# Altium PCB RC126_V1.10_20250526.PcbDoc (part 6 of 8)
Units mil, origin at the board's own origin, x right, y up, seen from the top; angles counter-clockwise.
Board outline 6299.62 x 3544.12 mil, 4 copper layers (Top, GND, Power, Bottom), stack 35.4 mil thick; 509 components, 417 nets, 1867 pads, 2150 vias.
Unrouted connection lines stored in the file: 1451.
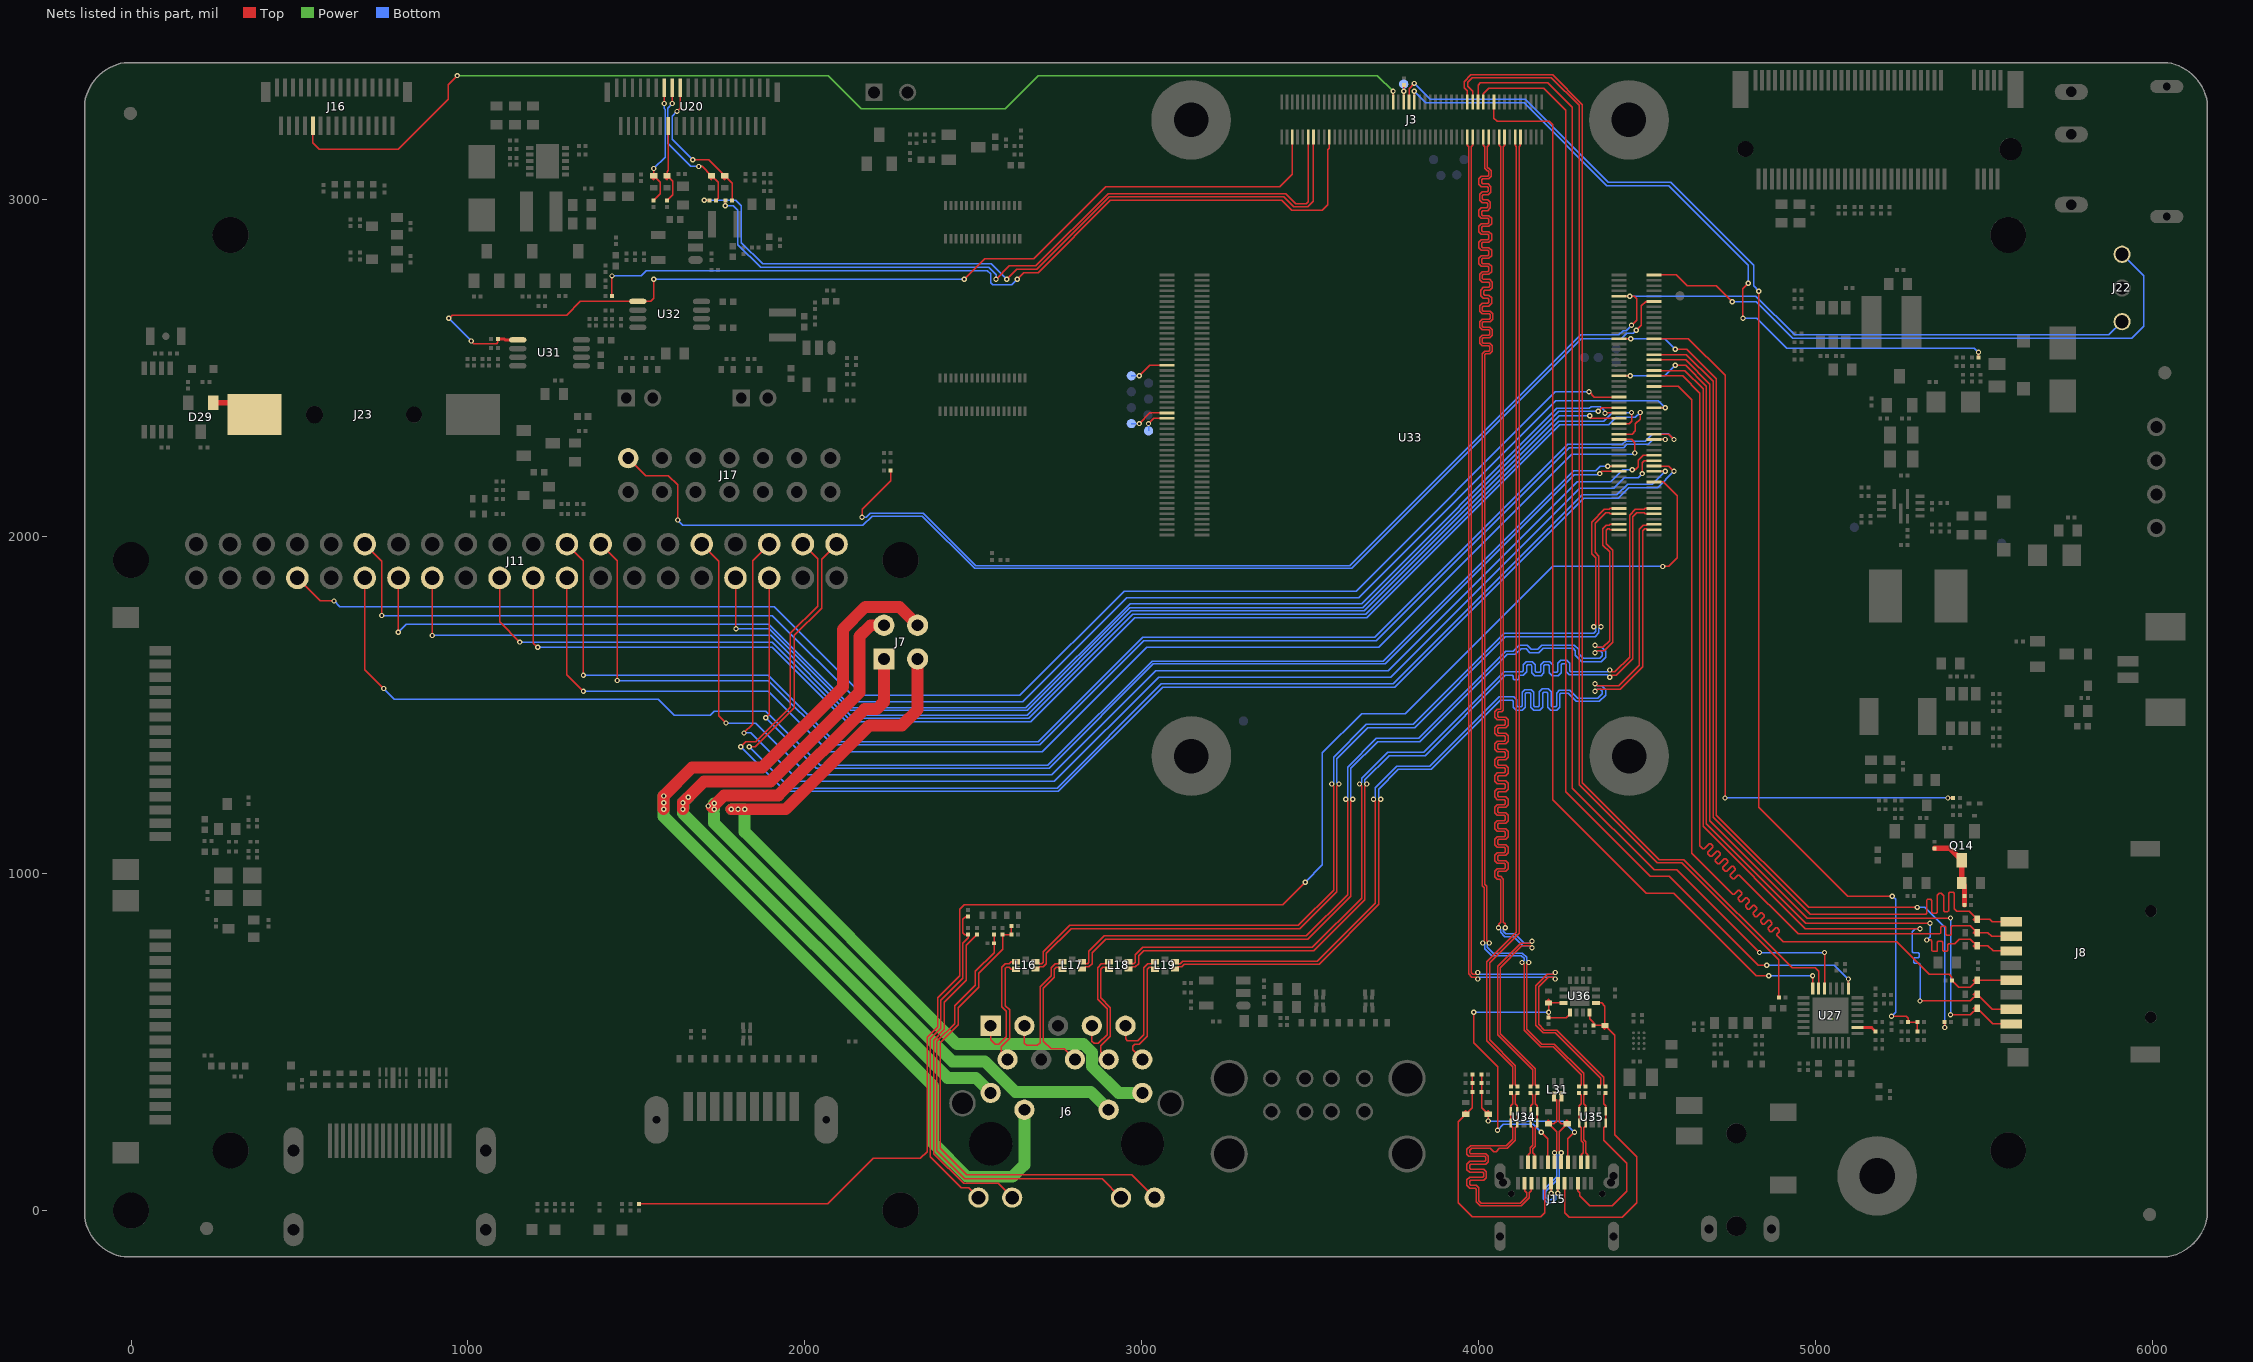
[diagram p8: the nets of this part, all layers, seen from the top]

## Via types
v1: diameter 15.75, hole 7.87, Top to Bottom, 2047 vias
v2: diameter 19.68, hole 11.81, Top to Bottom, 103 vias

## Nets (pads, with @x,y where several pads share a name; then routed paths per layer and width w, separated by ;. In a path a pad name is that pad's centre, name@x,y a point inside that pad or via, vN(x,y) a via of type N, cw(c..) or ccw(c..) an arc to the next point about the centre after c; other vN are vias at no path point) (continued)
PHY1_MDI0+: L16.1 U33.12 | length 2759.1
  Top w3.94: L16.1@2684.25,738.58 2690.94,738.58 2696.85,732.68 2702.76,732.68 2706.69,736.61 2706.69,767.72 2785.43,846.46 3464.43,846.46 3568.9,950.93 3568.9,1259.84 v1(3562.99,1265.75) ; v1(4340.55,1732.28) 4346.46,1738.19 4346.46,1937.01 4334.65,1948.82 4334.65,2043.31 4371.85,2080.51 4386.81,2080.51 4389.76,2083.46 U33.12@4415.35,2083.46
  Bottom w3.94: v1(3562.99,1265.75) 3568.9,1271.65 3568.9,1345.54 3666.27,1442.91 3804.98,1442.91 4074.66,1712.6 4340.41,1712.6 4346.46,1718.64 4346.46,1726.38 v1(4340.55,1732.28)
PHY1_MDI0-: L16.2 U33.10 | length 2759.1
  Top w3.94: L16.2@2684.25,716.93 2690.94,716.93 2696.85,722.83 2706.83,722.83 2716.54,732.54 2716.54,763.64 2789.51,836.61 3468.5,836.61 3578.74,946.85 3578.74,1259.84 v1(3584.65,1265.75) ; v1(4362.2,1732.28) 4356.3,1738.19 4356.3,1915.35 4356.3,1941.08 4344.49,1952.9 4344.49,2039.23 4375.93,2070.67 4386.81,2070.67 4389.76,2067.72 U33.10@4415.35,2067.72
  Bottom w3.94: v1(3584.65,1265.75) 3578.74,1271.65 3578.74,1341.47 3670.35,1433.07 3809.06,1433.07 4078.74,1702.76 4344.49,1702.76 4356.3,1714.57 4356.3,1726.38 v1(4362.2,1732.28)
PHY1_MDI1+: L17.1 U33.4 | length 2704.6
  Top w3.94: L17.1@2822.05,738.58 2826.77,738.58 2832.68,732.68 2838.44,732.68 2842.52,736.75 2842.52,769.69 2887.8,814.96 3488.19,814.96 3610.24,937.01 3610.24,1214.57 v1(3604.33,1220.47) ; v1(4344.49,1655.51) 4350.39,1661.42 4372.05,1661.42 4397.64,1687.01 4397.64,1935.04 4397.64,1958.8 4377.95,1978.49 4377.95,2019.35 4382.03,2023.43 4386.81,2023.43 4389.76,2020.47 U33.4@4415.35,2020.47
  Bottom w3.94: v1(3604.33,1220.47) 3610.24,1226.38 3610.24,1316.01 3695.8,1401.57 3820.73,1401.57 4079.58,1660.43 4102.36,1660.43 4119.09,1677.17 4143.7,1677.17 4155.51,1665.35 4174.14,1665.35 4186.94,1678.15 4283.53,1678.15 4296.26,1665.42 4296.26,1651.64 4309.12,1638.78 4359.11,1638.78 4366.14,1645.81 4366.14,1655.37 4360.1,1661.42 4350.39,1661.42 v1(4344.49,1655.51)
PHY1_MDI1-: L17.2 U33.6 | length 2737.2
  Top w3.94: L17.2@2822.05,716.93 2826.77,716.93 2832.68,722.83 2842.52,722.83 2852.36,732.68 2852.36,765.61 2891.87,805.12 3492.27,805.12 3620.08,932.93 3620.08,1214.57 v1(3625.98,1220.47) ; v1(4344.49,1677.17) 4350.39,1671.26 4367.97,1671.26 4387.8,1691.08 4387.8,1954.72 4368.11,1974.41 4368.11,2023.43 4377.95,2033.27 4386.81,2033.27 4389.76,2036.22 U33.6@4415.35,2036.22
  Bottom w3.94: v1(3625.98,1220.47) 3620.08,1226.38 3620.08,1311.94 3699.87,1391.73 3824.8,1391.73 4083.66,1650.59 4108.27,1650.59 4124.93,1667.25 4139.69,1667.25 4151.44,1655.51 4178.22,1655.51 4191.01,1668.31 4279.46,1668.31 4286.42,1661.35 4286.42,1647.57 4305.05,1628.94 4363.19,1628.94 4375.98,1641.73 4375.98,1659.45 4364.17,1671.26 4350.39,1671.26 v1(4344.49,1677.17)
PHY1_MDI2+: L18.1 U33.11 | length 2752.2
  Top w3.94: L18.1@2959.84,738.58 2964.57,738.58 2970.47,732.68 2976.24,732.68 2980.32,736.75 2980.32,759.84 3001.97,781.5 3505.91,781.5 3651.57,927.17 3651.57,1259.84 v1(3645.67,1265.75) ; v1(4387.8,1604.33) 4393.7,1598.43 4403.4,1598.43 4446.85,1641.87 4446.85,2062.94 4464.43,2080.51 4491.14,2080.51 4494.09,2083.46 U33.11@4520.08,2083.46
  Bottom w3.94: v1(3645.67,1265.75) 3651.57,1271.65 3651.57,1282.55 3729.26,1360.24 3836.47,1360.24 4075.65,1599.41 4128.94,1599.41 4131.89,1602.36 4131.89,1620.22 4140.61,1628.94 4158.6,1628.94 4167.32,1620.22 4167.32,1600.39 4170.28,1597.44 4180.12,1597.44 4183.07,1600.39 4183.07,1620.22 4191.79,1628.94 4209.79,1628.94 4218.5,1620.22 4218.5,1600.39 4221.46,1597.44 4231.3,1597.44 4234.25,1600.39 4234.25,1624.16 4242.97,1632.87 4260.97,1632.87 4269.68,1624.16 4269.68,1602.36 4272.64,1599.41 4382.87,1599.41 v1(4387.8,1604.33)
PHY1_MDI2-: L18.2 U33.9 | length 2772.9
  Top w3.94: L18.2@2959.84,716.93 2964.57,716.93 2970.47,722.83 2980.32,722.83 2990.16,732.68 2990.16,755.77 3006.05,771.65 3509.98,771.65 3661.42,923.09 3661.42,1259.84 v1(3667.32,1265.75) ; v1(4387.8,1582.68) 4393.7,1588.58 4407.48,1588.58 4456.69,1637.8 4456.69,2058.86 4468.5,2070.67 4491.14,2070.67 4494.09,2067.72 U33.9@4520.08,2067.72
  Bottom w3.94: v1(3667.32,1265.75) 3661.42,1271.65 3661.42,1278.47 3733.34,1350.39 3840.55,1350.39 4078.74,1588.58 4099.17,1588.58 4102.36,1585.39 4102.36,1578.08 4105.32,1575.13 4115.16,1575.13 4118.11,1578.08 4118.11,1585.63 4121.06,1588.58 4132.03,1588.58 4141.73,1598.29 4141.73,1616.14 4144.68,1619.09 4154.53,1619.09 4157.48,1616.14 4157.48,1596.32 4166.2,1587.6 4184.19,1587.6 4192.91,1596.32 4192.91,1616.14 4195.87,1619.09 4205.71,1619.09 4208.66,1616.14 4208.66,1596.32 4217.38,1587.6 4235.38,1587.6 4244.09,1596.32 4244.09,1620.08 4247.05,1623.03 4256.89,1623.03 4259.84,1620.08 4259.84,1598.29 4268.56,1589.57 4380.91,1589.57 v1(4387.8,1582.68)
PHY1_MDI3+: L19.1 U33.3 | length 2712.9
  Top w3.94: L19.1@3097.64,738.58 3102.36,738.58 3108.27,732.68 3114.03,732.68 3121.51,740.16 3520.53,740.16 3692.91,912.54 3692.91,1214.57 v1(3687.01,1220.47) ; v1(4344.49,1541.34) 4350.39,1547.24 4419.29,1547.24 4486.22,1614.17 4486.22,2017.38 4492.27,2023.43 4497.05,2023.43 4500,2020.47 U33.3@4520.08,2020.47
  Bottom w3.94: v1(3687.01,1220.47) 3692.91,1226.38 3692.91,1254.99 3756.82,1318.9 3854.19,1318.9 4059.9,1524.61 4103.49,1524.61 4112.2,1515.89 4112.2,1498.03 4115.16,1495.08 4125,1495.08 4127.95,1498.03 4127.95,1537.54 4136.67,1546.26 4154.67,1546.26 4163.39,1537.54 4163.39,1498.03 4166.34,1495.08 4176.18,1495.08 4179.13,1498.03 4179.13,1539.51 4187.85,1548.23 4205.85,1548.23 4214.57,1539.51 4214.57,1498.03 4217.52,1495.08 4227.36,1495.08 4230.32,1498.03 4230.32,1535.57 4239.03,1544.29 4269.75,1544.29 4293.38,1520.67 4353.21,1520.67 4366.14,1533.6 4366.14,1541.2 4360.1,1547.24 4350.39,1547.24 v1(4344.49,1541.34)
PHY1_MDI3-: L19.2 U33.5 | length 2745.8
  Top w3.94: L19.2@3097.64,716.93 3102.36,716.93 3108.27,722.83 3118.11,722.83 3125.59,730.32 3525.65,730.32 3702.76,908.46 3702.76,1214.57 v1(3708.66,1220.47) ; v1(4344.49,1562.99) 4350.39,1557.09 4415.21,1557.09 4476.38,1618.25 4476.38,2021.46 4488.19,2033.27 4497.05,2033.27 4500,2036.22 U33.5@4520.08,2036.22
  Bottom w3.94: v1(3708.66,1220.47) 3702.76,1226.38 3702.76,1250.91 3760.9,1309.06 3858.27,1309.06 4063.98,1514.76 4099.41,1514.76 4102.36,1511.81 4102.36,1493.95 4111.08,1485.24 4129.08,1485.24 4137.8,1493.95 4137.8,1533.46 4140.75,1536.42 4150.59,1536.42 4153.54,1533.46 4153.54,1493.95 4162.26,1485.24 4180.26,1485.24 4188.98,1493.95 4188.98,1535.43 4191.93,1538.39 4201.77,1538.39 4204.72,1535.43 4204.72,1493.95 4213.44,1485.24 4231.44,1485.24 4240.16,1493.95 4240.16,1531.5 4243.11,1534.45 4265.68,1534.45 4289.3,1510.83 4357.28,1510.83 4375.98,1529.53 4375.98,1545.28 4364.17,1557.09 4350.39,1557.09 v1(4344.49,1562.99)
PHY_G_LED+: J6.15 R248.1 R252.2 | length 975.5
  Top w3.94: R252.2@2484.25,872.05 2476.38,872.05 2468.5,864.17 2468.5,824.8 2474.41,818.9 R248.1@2484.25,818.9 2484.25,809.06 2468.5,793.31 2468.5,688.98 2403.54,624.02 2403.54,541.34 2372.05,509.84 2372.05,159.45 2464.17,67.32 2486.22,67.32 J6.15@2514.96,38.58
PHY_G_LED-: J6.16 R253.1 | length 989.8
  Top w3.94: R253.1@2509.84,818.9 2478.35,787.4 2478.35,683.07 2413.39,618.11 2413.39,537.4 2381.89,505.91 2381.89,169.29 2470.47,80.71 2572.83,80.71 J6.16@2614.96,38.58
PHY_MDI0+: J6.1 L16.3 | length 361.9
  Top w3.94: J6.1@2551.18,548.43 2551.18,506.89 2563.98,494.09 2575.72,494.09 2597.44,515.82 2597.44,591.4 2584.65,604.19 2584.65,658.32 2584.65,722.44 2594.49,732.28 2606.3,732.28 2612.2,738.19 L16.3@2625.98,738.19
PHY_MDI0-: J6.2 L16.4 | length 328.7
  Top w3.94: J6.2@2601.18,448.43 2582.68,466.93 2582.68,486.22 2607.28,510.83 2607.28,595.47 2594.49,608.27 2594.49,718.36 2598.57,722.44 2606.3,722.44 2612.2,716.54 L16.4@2625.98,716.54
PHY_MDI1+: J6.3 L17.3 | length 381.2
  Top w3.94: J6.3@2651.18,548.43 2651.18,496.46 2657.48,490.16 2689.96,490.16 2697.83,498.03 2697.83,664.51 2730.32,696.99 2730.32,720.47 2742.13,732.28 2751.97,732.28 2757.87,738.19 L17.3@2763.78,738.19
PHY_MDI1-: J6.6 L17.4 | length 371.6
  Top w3.94: L17.4@2763.78,716.54 2757.87,716.54 2751.97,722.44 2746.2,722.44 2740.16,716.4 2740.16,692.91 2707.68,660.43 2707.68,502.95 2730.32,480.32 2769.29,480.32 J6.6@2801.18,448.43
PHY_MDI2+: J6.7 L18.3 | length 355.7
  Top w3.94: J6.7@2851.18,548.43 2851.18,503.15 2858.27,496.06 2870.99,496.06 2896.65,521.72 2896.65,598.36 2868.11,626.9 2868.11,720.47 2879.92,732.28 2889.76,732.28 2895.67,738.19 L18.3@2901.57,738.19
PHY_MDI2-: J6.8 L18.4 | length 329.8
  Top w3.94: J6.8@2901.18,448.43 2877.95,471.65 2877.95,489.1 2906.5,517.65 2906.5,602.43 2877.95,630.98 2877.95,716.4 2884,722.44 2889.76,722.44 2895.67,716.54 L18.4@2901.57,716.54
PHY_MDI3+: J6.9 L19.3 | length 342.9
  Top w3.94: J6.9@2951.18,548.43 2951.18,509.45 2956.69,503.94 2988.05,503.94 3005.91,521.79 3005.91,720.47 3017.72,732.28 3027.56,732.28 3033.46,738.19 L19.3@3039.37,738.19
PHY_MDI3-: J6.10 L19.4 | length 334.5
  Top w3.94: J6.10@3001.18,448.43 2972.44,477.17 2972.44,488.19 2978.35,494.09 2992.13,494.09 3015.75,517.72 3015.75,590.55 3015.75,630.98 3015.75,716.4 3021.79,722.44 3027.56,722.44 3033.46,716.54 L19.4@3039.37,716.54
PHY_Y_LED+: J6.17 R238.2 R241.2 | length 1315.3
  Top w3.94: R241.2@2561.02,818.9 R238.2@2561.02,793.31 2561.02,765.75 2505.91,710.63 2505.91,668.92 2444.88,607.9 2444.88,555.12 2391.73,501.97 2391.73,177.17 2474.41,94.49 2881.89,94.49 J6.17@2937.8,38.58
PHY_Y_LED-: J6.18 R237.1 R239.2 R242.1 | length 1458.6
  Top w3.94: R242.1@2612.2,844.49 R239.2@2612.2,818.9 R237.1@2586.61,818.9 2586.61,775.59 2515.75,704.72 2515.75,663.39 2454.72,602.36 2454.72,551.18 2401.57,498.03 2401.57,185.04 2480.32,106.3 2970.08,106.3 J6.18@3037.8,38.58
PI_NLED_ACTIVITY: R227.2 U33.21 | length 4703.6
  Top w3.94: R227.2@1507.87,19.69 2066.93,19.69 2202.76,155.51 2342.52,155.51 2362.2,175.2 2362.2,513.78 2393.7,545.28 2393.7,631.89 2458.66,696.85 2458.66,893.7 2472.44,907.48 3417.32,907.48 v1(3484.25,974.41) ; U33.21@4520.08,2162.2 4547.24,2162.2 4588.58,2120.87 4588.58,1937.01 4562.99,1911.42 v1(4545.28,1911.42)
  Bottom w3.94: v1(3484.25,974.41) 3535.43,1025.59 3535.43,1358.27 3651.57,1474.41 3781.5,1474.41 4218.5,1911.42 v1(4545.28,1911.42)
PTP_CLKIN: P11.1 U33.166 | length 119.3
  Top w3.94: v1(2991.73,2477.17) 3023.23,2508.66 U33.166@3074.8,2508.66
  Bottom w3.94: P11.1@2968.5,2477.17 v1(2991.73,2477.17)
PWM1_CH0_M2: J11.13 U33.48 | length 4276.9
  Top w3.94: v1(793.31,1716.54) 793.31,1784.06 793.7,1784.45 J11.13@793.7,1877.56 ; v1(4374.02,2366.14) 4374.8,2366.93 U33.48@4415.35,2366.93
  Bottom w3.94: v1(793.31,1716.54) 816.93,1740.16 1891.79,1740.16 2139.82,1492.13 2655.66,1492.13 2964.72,1801.18 3651.57,1801.18 4230.93,2380.53 4327.38,2380.53 4332.68,2385.83 4360.04,2385.83 4369.91,2375.96 v1(4374.02,2366.14)
PWRON_L: J22.3 U33.99 | length 1785.6
  Top w3.94: U33.99@4520.08,2776.38 4585.83,2776.38 4618.11,2744.09 4704.72,2744.09 v1(4751.97,2696.85)
  Bottom w3.94: v1(4751.97,2696.85) 4822.83,2696.85 4931.1,2588.58 5937.4,2588.58 5972.83,2624.02 5972.83,2773.62 J22.3@5908.66,2837.8
REF_CLK0_OUT_1V8: J3.57 J16.22 | length 3512.5
  Top w3.94: J16.22@539.37,3219.5 539.37,3169.49 559.25,3149.61 793.31,3149.61 940.94,3297.24 940.94,3340.55 v1(968.5,3368.11) ; J3.57@3745.28,3289.77 3745.28,3290.9 v1(3745.28,3321.26)
  Power w3.94: v1(968.5,3368.11) 2068.9,3368.11 2167.32,3269.69 2594.49,3269.69 2692.91,3368.11 3698.43,3368.11 v1(3745.28,3321.26)
RESET_L: J22.1 R218.2 U33.92 | length 4490.1
  Top w3.94: v1(2169.29,2057.09) 2169.29,2080.71 2253.94,2165.35 R218.2@2253.94,2196.85 ; U33.92@4415.35,2713.39 v1(4447.24,2713.39) 4460.63,2713.39 4468.5,2705.51 4468.5,2642.52 v1(4452.76,2626.77)
  Bottom w3.94: v1(2169.29,2057.09) 2181.57,2057.09 2193.38,2068.9 2351.05,2068.9 2506.56,1913.39 3616.71,1913.39 4301.75,2598.43 4415.65,2598.43 4428.79,2611.56 4437.55,2611.56 v1(4452.76,2626.77) ; v1(4447.24,2713.39) 4822.05,2713.39 4937.01,2598.43 5869.29,2598.43 J22.1@5908.66,2637.8
RIN1_ES8388: C248.1 U27.23 | length 58
  Top w7.87: U27.23@5124.02,543.31 5165.35,543.31 C248.1@5177.17,531.5
RTC_BATTERY: D29.1 J23.1 | length 137
  Top w15.75: D29.1@244.09,2397.64 320.87,2397.64 348.43,2370.08 357.95,2370.08 J23.1@366.22,2361.81
SAI1_LRCK_M0: J3.19 U27.7 | length 3258.9
  Top w3.94: J3.19@4044.49,3289.77 4044.49,3275.7 4044.49,3242.13 4054.33,3232.28 4208.66,3232.28 4218.5,3222.44 4218.5,1218.5 4496.06,940.94 4578.74,940.94 4822.83,696.85 v1(4860.24,696.85) ; U27.7@4990.16,659.45 v1(4990.16,696.85)
  Bottom w3.94: v1(4860.24,696.85) v1(4990.16,696.85)
SAI1_MCLK_M0: J3.23 U27.1 | length 3422.7
  Top w3.94: J3.23@4013,3289.77 4013,3302.3 4012.99,3314.17 4029.53,3330.71 4192.91,3330.71 4257.87,3265.75 4257.87,1242.13 4507.87,992.13 4564.96,992.13 4828.74,728.35 v1(4854.33,728.35) ; U27.1@5096.46,659.45 v1(5096.46,687.01)
  Bottom w3.94: v1(4854.33,728.35) 5055.12,728.35 v1(5096.46,687.01)
SAI1_SCLK_M0: J3.25 U27.5 | length 3439.5
  Top w3.94: J3.25@3997.25,3289.77 3997.25,3300.9 3997.24,3339.76 4003.94,3346.46 4204.72,3346.46 4277.56,3273.62 4277.56,1253.94 4519.68,1011.81 4586.61,1011.81 v1(4832.68,765.75) ; U27.5@5025.59,659.45 v1(5025.59,765.75)
  Bottom w3.94: v1(4832.68,765.75) v1(5025.59,765.75)
SAI1_SDI0_M0: J3.27 R276.1 | length 3371.3
  Top w3.94: J3.27@3981.5,3289.77 3981.5,3301 3981.5,3321.65 3966.54,3336.61 3966.54,3348.43 3980.32,3362.2 4214.57,3362.2 4297.24,3279.53 4297.24,1263.78 4529.53,1031.5 4602.36,1031.5 4889.76,744.09 R276.1@4889.76,631.89
SAI1_SDO0_M0: J3.29 U27.6 | length 3455
  Top w3.94: J3.29@3965.75,3289.77 3965.75,3302.2 3965.75,3323.62 3956.69,3332.68 3956.69,3350.39 3976.38,3370.08 4218.5,3370.08 4307.09,3281.5 4307.09,1269.69 4535.43,1041.34 4608.27,1041.34 4929.13,720.47 4998.03,720.47 5007.88,710.63 U27.6@5007.88,659.45
SAI2_LRCK_M0: J11.35 U33.26 | length 3377.3
  Top w3.94: v1(1883.86,1462.6) 1893.7,1472.44 J11.35@1893.7,1877.56 ; v1(4358.27,2187.01) 4364.96,2193.7 U33.26@4415.35,2193.7
  Bottom w3.94: v1(1883.86,1462.6) 2033.46,1312.99 2724.41,1312.99 3033.46,1622.05 3722.44,1622.05 4283.46,2183.07 4354.33,2183.07 v1(4358.27,2187.01)
SAI2_MCLK_M0: J11.36 U33.29 | length 3765
  Top w3.94: v1(1818.9,1417.32) 1844.49,1442.91 1844.49,1928.35 J11.36@1893.7,1977.56 ; v1(4484.25,2187.01) 4484.25,2219.29 4490.16,2225.2 U33.29@4520.08,2225.2
  Bottom w3.94: v1(1818.9,1417.32) 1838.58,1417.32 1982.28,1273.62 2740.16,1273.62 3049.21,1582.68 3738.19,1582.68 4299.21,2143.7 4399.61,2143.7 4431.1,2175.2 4472.44,2175.2 v1(4484.25,2187.01)
SAI2_SCLK_M0: J11.12 U33.49 | length 4559.6
  Top w3.94: J11.12@693.7,1977.56 744.09,1927.17 v1(744.09,1765.75) ; U33.49@4520.08,2382.68 v1(4553.15,2382.68)
  Bottom w3.94: v1(744.09,1765.75) 1903.54,1765.75 2159.45,1509.84 2645.67,1509.84 2954.72,1818.9 3643.7,1818.9 4228.35,2403.54 4532.28,2403.54 v1(4553.15,2382.68)
SAI2_SDI_M0: J11.38 U33.27 | length 4014.4
  Top w3.94: v1(1809.06,1375.98) 1824.8,1391.73 1854.33,1391.73 1956.69,1494.09 1956.69,1712.6 2037.4,1793.31 2037.4,1933.86 J11.38@1993.7,1977.56 ; U33.27@4520.08,2209.45 4562.99,2209.45 v1(4578.74,2193.7)
  Bottom w3.94: v1(1809.06,1375.98) 1940.94,1244.09 2751.97,1244.09 3061.02,1553.15 3750,1553.15 4311.02,2114.17 4413.39,2114.17 4444.88,2145.67 4530.71,2145.67 v1(4578.74,2193.7)
SAI2_SDO_M0: J11.40 U33.25 | length 3910.6
  Top w3.94: v1(1834.65,1375.98) 1852.36,1375.98 1968.5,1492.13 1968.5,1706.69 2049.21,1787.4 2049.21,1933.07 J11.40@2093.7,1977.56 ; U33.25@4520.08,2193.7 v1(4553.15,2193.7)
  Bottom w3.94: v1(1834.65,1375.98) 1956.69,1253.94 2748.03,1253.94 3057.09,1562.99 3746.06,1562.99 4307.09,2124.02 4409.45,2124.02 4440.94,2155.51 4514.96,2155.51 v1(4553.15,2193.7)
SARADC_VIN1_KEY/RECOVERY: J17.2 U33.89 | length 3625.5
  Top w3.94: J17.2@1475.59,2232.68 1527.17,2181.1 1594.49,2181.1 1622.05,2153.54 v1(1622.05,2049.21) ; v1(4466.54,2612.2) 4482.28,2627.95 4482.28,2685.04 4494.88,2697.64 U33.89@4520.08,2697.64
  Bottom w3.94: v1(1622.05,2049.21) 1637.8,2033.46 2171.49,2033.46 2199.05,2061.02 2347.77,2061.02 2503.28,1905.51 3622.9,1905.51 4304.01,2586.61 4422.74,2586.61 4439.34,2603.21 4457.54,2603.21 v1(4466.54,2612.2)
SARADC_VIN3_HP_HOOK_1V8: C281.1 J3.51 R305.2 R319.1 | length 3895.5
  Top w3.94: J3.51@3792.52,3289.77 3792.52,3302.7 3792.52,3329.13 v1(3808.27,3344.88) ; v1(4830.71,2728.35) 4830.71,1196.85 5094.49,933.07 v1(5226.38,933.07) ; v1(5224.41,576.77) 5267.72,576.77 5273.62,570.87 R305.2@5273.62,559.06 R319.1@5301.18,559.06 C281.1@5301.18,531.5
  Bottom w3.94: v1(3808.27,3344.88) 3855.91,3297.24 4137.8,3297.24 4383.86,3051.18 4568.9,3051.18 4814.96,2805.12 4814.96,2744.09 v1(4830.71,2728.35) ; v1(5224.41,576.77) 5236.22,588.58 5236.22,923.23 v1(5226.38,933.07)
SARADC_VIN5_BOM_ID: J3.53 P20.1 R72.1 | length 75.9
  Top w3.94: J3.53@3776.78,3289.77 3777.9,3288.64 3777.9,3299.17 3776.77,3300.3 v1(3776.77,3321.26) 3776.77,3339.76 R72.1@3777.56,3340.55
  Bottom w3.94: v1(3776.77,3321.26) P20.1@3776.77,3342.91
SARADC_VIN7_1V8: J3.49 R178.1 | length 2156.4
  Top w3.94: J3.49@3808.27,3289.77 3808.27,3303.6 v1(3808.27,3321.26) ; v1(4783.46,2647.64) 4783.46,2736.22 v1(4799.21,2751.97) ; R178.1@5482.28,2531.5 v1(5482.28,2547.24)
  Bottom w3.94: v1(3808.27,3321.26) 3842.13,3287.4 4133.86,3287.4 4379.92,3041.34 4562.99,3041.34 4799.21,2805.12 v1(4799.21,2751.97) ; v1(4783.46,2647.64) 4824.8,2647.64 4913.39,2559.06 5470.47,2559.06 v1(5482.28,2547.24)
SD_3V3: C171.1 C172.1 Q14.3 R31.1 R231.2 | length 230.5
  Top w15.75: R231.2@5352.36,1074.8 5397.63,1074.8 Q14.3@5433.07,1039.37 C172.1@5433.07,972.44 5440.94,964.57 C171.1@5440.94,933.07 R31.1@5440.94,907.48
SDMMC0_CLK: C170.1 D21.2 J8.5 U33.57 | length 2812.2
  Top w3.94: U33.57@4520.08,2445.67 4591.73,2445.67 4631.89,2405.51 4631.89,1060.76 4753.58,939.07 4757.75,939.07 4769.02,950.33 4773.19,950.33 4780.15,943.37 4780.15,939.19 4768.89,927.93 4768.89,923.76 4775.85,916.8 4780.03,916.8 4791.29,928.06 4795.46,928.06 4802.42,921.1 4802.42,916.92 4791.16,905.66 4791.16,901.49 4798.12,894.53 4802.3,894.53 4813.56,905.79 4817.73,905.79 4824.69,898.83 4824.69,894.65 4813.43,883.39 4813.43,879.21 4820.39,872.26 4824.57,872.26 4835.83,883.52 4840,883.52 4846.96,876.56 4846.96,872.38 4835.7,861.12 4835.7,856.94 4842.66,849.98 4846.84,849.98 4858.1,861.25 4862.28,861.25 4869.24,854.29 4869.24,850.11 4857.97,838.85 4857.97,834.67 4864.93,827.71 4869.11,827.71 4880.37,838.97 4884.55,838.97 4891.51,832.01 4891.51,827.84 4884.32,820.65 4884.32,816.47 4903.54,797.24 5240.16,797.24 5336.61,700.79 5395.67,700.79 5403.54,692.91 C170.1@5403.54,683.07 5423.23,663.39 5458.66,663.39 D21.2@5478.35,683.07 5479.13,683.86 J8.5@5579.7,683.86
SDMMC0_CMD: D17.2 J8.3 U33.62 | length 2808.4
  Top w3.94: U33.62@4415.35,2477.17 v1(4448.82,2477.17) ; v1(4582.68,2508.66) 4613.39,2508.66 4675.2,2446.85 4675.2,1147.64 4970.47,852.36 v1(5338.58,852.36) ; v1(5328.74,803.15) 5340.85,803.15 5344.49,799.51 5344.49,771.65 5346.46,769.69 5358.27,769.69 5360.24,771.65 5360.24,795.87 5363.19,798.83 5373.03,798.83 5375.98,795.87 5375.98,772.45 5378.94,769.5 5388.78,769.5 5391.73,772.45 5391.73,788.39 5394.68,791.34 5411.42,791.34 5425.2,805.12 5458.66,805.12 D17.2@5478.35,785.43 5510.63,785.43 5525.59,770.47 J8.3@5579.7,770.47
  Bottom w3.94: v1(4448.82,2477.17) 4551.18,2477.17 v1(4582.68,2508.66) ; v1(5328.74,803.15) 5338.58,812.99 v1(5338.58,852.36)
SDMMC0_D0: D20.2 J8.7 U33.63 | length 2811.1
  Top w3.94: U33.63@4520.08,2492.91 4611.42,2492.91 4665.35,2438.98 4665.35,1139.76 4968.5,836.61 v1(5309.06,836.61) ; v1(5309.06,622.05) 5458.66,622.05 D20.2@5478.35,641.73 5522.83,597.24 J8.7@5579.7,597.24
  Bottom w3.94: v1(5309.06,622.05) 5309.06,731 5305.81,734.25 5293.5,734.25 5290.55,737.2 5290.55,747.05 5293.5,750 5303.71,750 5306.67,752.95 5306.67,762.8 5303.71,765.75 5288.39,765.75 5285.43,768.7 5285.43,826.77 5295.28,836.61 v1(5309.06,836.61)
SDMMC0_D1: D19.2 J8.8 U33.67 | length 2819.2
  Top w3.94: U33.67@4520.08,2524.41 4613.39,2524.41 4685.04,2452.76 4685.04,1157.48 4974.41,868.11 v1(5399.61,868.11) ; v1(5399.61,580.71) 5458.66,580.71 D19.2@5478.35,600.39 5524.8,553.94 J8.8@5579.7,553.94
  Bottom w3.94: v1(5399.61,580.71) v1(5399.61,868.11)
SDMMC0_D2/JTAG_TCK_M0: D22.2 J8.1 U33.69 | length 2803.6
  Top w3.94: U33.69@4520.08,2540.16 4615.35,2540.16 4694.88,2460.63 4694.88,1167.32 4983.58,878.62 5325.79,878.62 5328.74,881.57 5328.74,921.26 5330.71,923.23 5340.55,923.23 5344.49,919.29 5344.49,885.19 5347.44,882.24 5357.28,882.24 5360.24,885.19 5360.24,935.04 5366.14,940.94 5372.05,940.94 5378.94,934.06 5378.94,889.76 5382.36,886.34 5389.76,886.34 5393.7,890.27 5393.7,940.94 5397.64,944.88 5407.48,944.88 5410.43,941.93 5410.43,895.67 5418.31,887.8 5454.72,887.8 D22.2@5478.35,864.17 5516.54,864.17 5523.62,857.09 J8.1@5579.7,857.09
SDMMC0_D3/JTAG_TMS_M0: D23.2 J8.2 U33.61 | length 2814.2
  Top w3.94: U33.61@4520.08,2477.17 4604.33,2477.17 4655.51,2425.98 4655.51,1082.11 4663.8,1073.82 4667.98,1073.82 4683.03,1088.87 4687.2,1088.87 4694.16,1081.91 4694.16,1077.73 4679.11,1062.68 4679.11,1058.51 4686.07,1051.55 4690.25,1051.55 4705.3,1066.59 4709.47,1066.59 4716.43,1059.64 4716.43,1055.46 4701.38,1040.41 4701.38,1036.24 4708.34,1029.28 4712.52,1029.28 4727.57,1044.32 4731.74,1044.32 4738.7,1037.36 4738.7,1033.19 4723.66,1018.14 4723.66,1013.96 4730.62,1007 4734.79,1007 4749.84,1022.05 4754.02,1022.05 4760.98,1015.09 4760.98,1010.92 4745.93,995.87 4745.93,991.69 4752.89,984.73 4757.06,984.73 4767.93,995.61 4772.11,995.61 4946.85,820.87 5368.11,820.87 5370.08,822.83 5370.08,841.37 5373.03,844.32 5382.87,844.32 5385.83,841.37 5385.83,819.29 5388.78,816.34 5398.62,816.34 5401.57,819.29 5401.57,841.54 5404.53,844.49 5458.66,844.49 D23.2@5478.35,824.8 5510.63,824.8 5521.65,813.78 J8.2@5579.7,813.78
SDMMC0_DET_L: R228.1 U33.76 | length 2761.9
  Top w3.94: U33.76@4415.35,2587.4 v1(4450.79,2587.4) ; v1(4582.68,2555.91) 4617.32,2555.91 4704.72,2468.5 4704.72,1173.23 4978.35,899.61 v1(5301.18,899.61) ; v1(5381.89,543.31) R228.1@5381.89,559.06
  Bottom w3.94: v1(4450.79,2587.4) 4551.18,2587.4 v1(4582.68,2555.91) ; v1(5301.18,899.61) 5322.83,899.61 5381.89,840.55 v1(5381.89,543.31)
SDMMC0_PWREN_H: R230.1 U33.75 | length 2186.5
  Top w3.94: U33.75@4520.08,2587.4 4621.26,2587.4 4730.32,2478.35 v1(4730.32,1224.41) ; v1(5391.73,1224.41) R230.1@5407.48,1224.41
  Bottom w3.94: v1(4730.32,1224.41) v1(5391.73,1224.41)
SDS_IN_N: P5.1 U33.148 | length 119.3
  Top w3.94: v1(2991.73,2335.43) 3023.23,2366.93 U33.148@3074.8,2366.93
  Bottom w3.94: P5.1@2968.5,2335.43 v1(2991.73,2335.43)
SDS_IN_P: P4.1 U33.146 | length 83.9
  Top w3.94: v1(3019.29,2335.43) 3035.04,2351.18 U33.146@3074.8,2351.18
  Bottom w3.94: v1(3019.29,2335.43) 3019.68,2335.04 P4.1@3019.68,2313.78
SPI1_CLK_M0: J11.23 U33.38 | length 3999.3
  Top w3.94: J11.23@1293.7,1877.56 1293.7,1590.55 1342.52,1541.73 v1(1342.52,1541.34) ; U33.38@4415.35,2288.19 4452.76,2288.19 4462.6,2278.35 v1(4462.6,2248.03)
  Bottom w3.94: v1(1342.52,1541.34) 1891.73,1541.34 2070.87,1362.2 2704.72,1362.2 3013.78,1671.26 3702.76,1671.26 4275.59,2244.09 4458.66,2244.09 v1(4462.6,2248.03)
SPI1_CSN0_M0: J11.24 U33.39 | length 4177.5
  Top w3.94: J11.24@1293.7,1977.56 1342.52,1928.74 v1(1342.52,1588.58) ; U33.39@4520.08,2303.94 4562.99,2303.94 v1(4578.74,2288.19)
  Bottom w3.94: v1(1342.52,1588.58) 1891.73,1588.58 2088.58,1391.73 2692.91,1391.73 3001.97,1700.79 3690.94,1700.79 4263.78,2273.62 4425.2,2273.62 4435.04,2283.46 4494.09,2283.46 4515.75,2305.12 4561.81,2305.12 v1(4578.74,2288.19)
SPI1_CSN1_M0: J11.26 U33.37 | length 4022.9
  Top w3.94: J11.26@1393.7,1977.56 1442.91,1928.35 v1(1442.91,1572.83) ; U33.37@4520.08,2288.19 v1(4553.15,2288.19)
  Bottom w3.94: v1(1442.91,1572.83) 1891.73,1572.83 2082.68,1381.89 2696.85,1381.89 3005.91,1690.94 3694.88,1690.94 4267.72,2263.78 4429.13,2263.78 4438.98,2273.62 4503.15,2273.62 4517.72,2288.19 v1(4553.15,2288.19)
SPI1_MISO_M0: J11.21 U33.40 | length 4068
  Top w3.94: J11.21@1193.7,1877.56 1193.7,1684.25 v1(1206.69,1671.26) ; U33.40@4415.35,2303.94 4454.72,2303.94 4464.57,2313.78 4464.57,2334.65 4478.35,2348.43 v1(4478.35,2368.11)
  Bottom w3.94: v1(1206.69,1671.26) 1903.54,1671.26 2124.02,1450.79 2669.29,1450.79 2978.35,1759.84 3667.32,1759.84 4240.16,2332.68 4385.83,2332.68 4407.48,2354.33 4464.57,2354.33 v1(4478.35,2368.11)
SPI1_MOSI_M0: J11.19 U33.44 | length 4050.1
  Top w3.94: J11.19@1093.7,1877.56 1093.7,1746.85 v1(1153.54,1687.01) ; U33.44@4415.35,2335.43 4445.67,2335.43 4452.76,2342.52 v1(4452.76,2368.11)
  Bottom w3.94: v1(1153.54,1687.01) 1902.64,1687.01 2129.02,1460.63 2664.18,1460.63 2973.24,1769.69 3663.39,1769.69 4236.22,2342.52 4370.32,2342.52 4395.91,2368.11 v1(4452.76,2368.11)
SPI2_CLK_M1: J11.32 U33.31 | length 3782.5
  Top w3.94: J11.32@1693.7,1977.56 1744.09,1927.17 1744.09,1468.5 v1(1765.75,1446.85) ; v1(4454.72,2198.82) 4464.57,2198.82 4472.44,2206.69 4472.44,2226.38 4487.01,2240.94 U33.31@4520.08,2240.94
  Bottom w3.94: v1(1765.75,1446.85) 1854.33,1446.85 2007.87,1293.31 2732.28,1293.31 3041.34,1602.36 3730.32,1602.36 4291.34,2163.39 4391.73,2163.39 4427.17,2198.82 v1(4454.72,2198.82)
SPI2_CSN0_M1: J11.7 U33.54 | length 4445.3
  Top w3.94: J11.7@493.7,1877.56 562.2,1809.06 v1(602.36,1809.06) ; v1(4326.77,2429.92) 4342.52,2414.17 U33.54@4415.35,2414.17
  Bottom w3.94: v1(602.36,1809.06) 620.08,1791.34 1909.45,1791.34 2171.26,1529.53 2637.8,1529.53 2946.85,1838.58 3635.83,1838.58 4227.17,2429.92 v1(4326.77,2429.92)
SPI2_CSN1_M1: J11.33 U33.50 | length 3244.3
  Top w3.94: J11.33@1793.7,1877.56 1793.7,1875.59 1795.28,1874.02 v1(1795.28,1726.38) ; v1(4354.33,2372.05) 4364.96,2382.68 U33.50@4415.35,2382.68
  Bottom w3.94: v1(1795.28,1726.38) 1894.43,1726.38 2136.56,1484.25 2658.93,1484.25 2964.04,1789.37 3654.53,1789.37 4237.21,2372.05 v1(4354.33,2372.05)
SPI2_MISO_M1: J11.15 U33.46 | length 4164.4
  Top w3.94: v1(893.7,1706.69) J11.15@893.7,1877.56 ; v1(4328.74,2358.27) 4332.68,2354.33 4331.69,2353.35 4333.86,2351.18 U33.46@4415.35,2351.18
  Bottom w3.94: v1@894.69,1707.68 v1(893.7,1706.69) 1897.81,1706.69 2134.03,1470.47 2659.08,1470.47 2968.13,1779.53 3659.45,1779.53 4238.19,2358.27 v1(4328.74,2358.27)
SPI2_MOSI_M1: J11.11 U33.28 | length 4489.5
  Top w3.94: J11.11@693.7,1877.56 693.7,1605.51 v1(750,1549.21) ; v1(4381.89,2208.66) 4382.68,2209.45 U33.28@4415.35,2209.45
  Bottom w3.94: v1(750,1549.21) 781.5,1517.72 1564.96,1517.72 1612.2,1470.47 1718.5,1470.47 1730.32,1482.28 1883.86,1482.28 2045.28,1320.87 2721.15,1320.87 3030.2,1629.92 3716.54,1629.92 4281.5,2194.88 4346.65,2194.88 4360.43,2208.66 v1(4381.89,2208.66)
SPK_CTL_H: J3.96 R333.1 U31.1 U32.1 | length 3073
  Top w3.94: v1(942.91,2647.64) 952.76,2657.48 1293.31,2657.48 1333.67,2697.84 U32.1@1503.94,2697.84 1542.33,2697.84 1551.18,2706.69 v1(1551.18,2763.78) ; v1(1009.84,2580.71) 1017.72,2572.83 1084.65,2572.83 1088.58,2576.77 R333.1@1088.58,2586.61 ; v1(2472.44,2763.78) 2533.46,2824.8 2679.13,2824.8 2891.83,3037.5 3408.76,3037.5 3446.06,3074.8 3446.06,3181.4 J3.96@3446.07,3185.83
  Top w7.87: R333.1@1088.58,2586.61 1107.29,2586.61 1110.24,2583.67 U31.1@1147.64,2583.67
  Bottom w3.94: v1(942.91,2647.64) v1(1009.84,2580.71) ; v1(1551.18,2763.78) v1(2472.44,2763.78)
SSRX1N_DP_TX_D0N: J3.12 R346.1 | length 2890
  Top w3.94: R346.1@4094.49,368.11 4100.39,374.02 4100.39,427.17 4023.62,503.94 4023.62,738.19 4111.42,825.98 4111.42,3157.48 4107.48,3161.42 J3.12@4107.48,3185.83
SSRX1P_DP_TX_D0P: J3.10 R347.1 | length 2890
  Top w3.94: R347.1@4114.17,368.11 4108.27,374.02 4108.27,430.43 4031.5,507.2 4031.5,734.93 4119.29,822.72 4119.29,3157.48 4123.23,3161.42 J3.10@4123.23,3185.83
SSRX2N_DP_TX_D2N: J3.24 R348.1 | length 3534
  Top w3.94: v1(4011.02,794.09) 4015.75,798.82 4015.75,958.47 4009.84,964.37 4009.84,2538.58 4009.84,2542.83 4017.41,2550.39 4028.54,2550.39 4031.5,2553.35 4031.5,2563.19 4028.54,2566.14 4009.53,2566.14 4001.97,2573.71 4001.97,2590.07 4009.53,2597.64 4028.54,2597.64 4031.5,2600.59 4031.5,2610.43 4028.54,2613.39 4009.53,2613.39 4001.97,2620.95 4001.97,2637.32 4009.53,2644.88 4030.51,2644.88 4033.46,2647.83 4033.46,2657.68 4030.51,2660.63 4009.53,2660.63 4001.97,2668.2 4001.97,2684.56 4009.53,2692.13 4026.57,2692.13 4029.53,2695.08 4029.53,2704.92 4026.57,2707.87 4013.47,2707.87 4005.91,2715.44 4005.91,2731.8 4013.47,2739.37 4028.54,2739.37 4031.5,2742.32 4031.5,2752.17 4028.54,2755.12 4009.53,2755.12 4001.97,2762.68 4001.97,2779.05 4009.53,2786.61 4026.57,2786.61 4029.53,2789.57 4029.53,2799.41 4026.57,2802.36 4007.57,2802.36 4000,2809.93 4000,2826.29 4007.57,2833.86 4026.57,2833.86 4029.53,2836.81 4029.53,2846.65 4026.57,2849.61 4007.57,2849.61 4000,2857.17 4000,2873.54 4007.57,2881.1 4026.57,2881.1 4029.53,2884.06 4029.53,2893.9 4026.57,2896.85 4007.57,2896.85 4000,2904.42 4000,2920.78 4007.57,2928.35 4026.57,2928.35 4029.53,2931.3 4029.53,2941.14 4026.57,2944.09 4007.57,2944.09 4000,2951.66 4000,2968.03 4007.57,2975.59 4022.64,2975.59 4025.59,2978.54 4025.59,2988.39 4022.64,2991.34 4009.53,2991.34 4001.97,2998.9 4001.97,3015.27 4009.53,3022.83 4024.61,3022.83 4027.56,3025.79 4027.56,3035.63 4024.61,3038.58 4007.57,3038.58 4000,3046.15 4000,3062.51 4007.57,3070.08 4025.79,3070.08 4028.74,3073.03 4028.74,3082.87 4025.79,3085.83 4024.49,3085.83 4016.93,3093.39 4016.93,3157.48 4012.99,3161.42 J3.24@4013,3185.83 ; v1(4127.95,736.22) 4133.86,730.32 4133.86,535.43 4183.07,486.22 4220.47,486.22 4303.15,403.54 4303.15,374.02 R348.1@4297.24,368.11
  Bottom w3.94: v1(4011.02,794.09) 4016.93,788.19 4016.93,777.56 4038.58,755.91 4125.98,755.91 4133.86,748.03 4133.86,742.13 v1(4127.95,736.22)
SSRX2P_DP_TX_D2P: J3.22 R349.1 | length 3535
  Top w3.94: J3.22@4028.74,3185.83 4028.74,3161.42 4024.8,3157.48 4024.8,3096.65 4027.76,3093.7 4029.05,3093.7 4036.61,3086.14 4036.61,3069.77 4029.05,3062.2 4010.83,3062.2 4007.87,3059.25 4007.87,3049.41 4010.83,3046.46 4027.87,3046.46 4035.43,3038.89 4035.43,3022.53 4027.87,3014.96 4012.8,3014.96 4009.84,3012.01 4009.84,3002.17 4012.8,2999.21 4025.9,2999.21 4033.46,2991.65 4033.46,2975.28 4025.9,2967.72 4010.83,2967.72 4007.87,2964.76 4007.87,2954.92 4010.83,2951.97 4029.84,2951.97 4037.4,2944.4 4037.4,2928.04 4029.84,2920.47 4010.83,2920.47 4007.87,2917.52 4007.87,2907.68 4010.83,2904.72 4029.84,2904.72 4037.4,2897.16 4037.4,2880.79 4029.84,2873.23 4010.83,2873.23 4007.87,2870.28 4007.87,2860.43 4010.83,2857.48 4029.84,2857.48 4037.4,2849.92 4037.4,2833.55 4029.84,2825.98 4010.83,2825.98 4007.87,2823.03 4007.87,2813.19 4010.83,2810.24 4029.84,2810.24 4037.4,2802.67 4037.4,2786.31 4029.84,2778.74 4012.8,2778.74 4009.84,2775.79 4009.84,2765.94 4012.8,2762.99 4031.8,2762.99 4039.37,2755.43 4039.37,2739.06 4031.8,2731.5 4016.73,2731.5 4013.78,2728.54 4013.78,2718.7 4016.73,2715.75 4029.84,2715.75 4037.4,2708.18 4037.4,2691.82 4029.84,2684.25 4012.8,2684.25 4009.84,2681.3 4009.84,2671.46 4012.8,2668.5 4033.77,2668.5 4041.34,2660.94 4041.34,2644.57 4033.77,2637.01 4012.8,2637.01 4009.84,2634.06 4009.84,2624.21 4012.8,2621.26 4031.8,2621.26 4039.37,2613.69 4039.37,2597.33 4031.8,2589.76 4012.8,2589.76 4009.84,2586.81 4009.84,2576.97 4012.8,2574.02 4031.8,2574.02 4039.37,2566.45 4039.37,2550.08 4031.8,2542.52 4020.67,2542.52 4017.72,2539.57 4017.72,2538.58 4017.72,967.63 4023.62,961.73 4023.62,801.18 v1(4030.71,794.09) ; v1(4147.64,736.22) 4141.73,730.32 4141.73,538.69 4186.33,494.09 4223.73,494.09 4311.02,406.8 4311.02,374.02 R349.1@4316.93,368.11
  Bottom w3.94: v1(4030.71,794.09) 4024.8,788.19 4024.8,780.82 4041.84,763.78 4129.25,763.78 4141.73,751.29 4141.73,750 4141.73,742.13 v1(4147.64,736.22)
SSTX1N_DP_TX_D1N: C251.1 J3.18 | length 3531.1
  Top w3.94: v1(4058.27,839.37) 4058.55,839.37 4058.55,850.39 4064.32,856.16 4064.32,980.65 4061.36,983.61 4054.81,983.61 4047.24,991.17 4047.24,1007.54 4054.81,1015.1 4075.79,1015.1 4078.74,1018.06 4078.74,1027.9 4075.79,1030.85 4054.81,1030.85 4047.24,1038.42 4047.24,1054.78 4054.81,1062.35 4075.79,1062.35 4078.74,1065.3 4078.74,1075.14 4075.79,1078.1 4054.81,1078.1 4047.24,1085.66 4047.24,1102.03 4054.81,1109.59 4075.79,1109.59 4078.74,1112.54 4078.74,1122.39 4075.79,1125.34 4054.81,1125.34 4047.24,1132.9 4047.24,1149.27 4054.81,1156.84 4075.79,1156.84 4078.74,1159.79 4078.74,1169.63 4075.79,1172.58 4054.81,1172.58 4047.24,1180.15 4047.24,1196.51 4054.81,1204.08 4075.79,1204.08 4078.74,1207.03 4078.74,1216.87 4075.79,1219.83 4054.81,1219.83 4047.24,1227.39 4047.24,1243.76 4054.81,1251.32 4075.79,1251.32 4078.74,1254.28 4078.74,1264.12 4075.79,1267.07 4054.81,1267.07 4047.24,1274.64 4047.24,1291 4054.81,1298.57 4075.79,1298.57 4078.74,1301.52 4078.74,1311.36 4075.79,1314.32 4054.81,1314.32 4047.24,1321.88 4047.24,1338.25 4054.81,1345.81 4075.79,1345.81 4078.74,1348.76 4078.74,1358.61 4075.79,1361.56 4054.81,1361.56 4047.24,1369.12 4047.24,1385.49 4054.81,1393.06 4075.79,1393.06 4078.74,1396.01 4078.74,1405.85 4075.79,1408.8 4054.81,1408.8 4047.24,1416.37 4047.24,1432.73 4054.81,1440.3 4075.79,1440.3 4078.74,1443.25 4078.74,1453.1 4075.79,1456.05 4054.81,1456.05 4047.24,1463.61 4047.24,1479.98 4054.81,1487.54 4062.99,1487.54 4064.17,1488.72 4064.17,3157.48 4060.24,3161.42 J3.18@4060.24,3185.83 ; v1(4157.48,779.53) 4151.57,785.43 4127.28,785.43 4062.99,721.15 4062.99,524.91 4167.32,420.58 4167.32,374.02 C251.1@4173.23,368.11
  Bottom w3.94: v1(4058.27,839.37) 4064.17,833.46 4064.17,826.77 4064.17,825.48 4076.66,812.99 4103.04,812.99 4130.6,785.43 4133.86,785.43 4151.57,785.43 v1(4157.48,779.53)
SSTX1P_DP_TX_D1P: C252.1 J3.16 | length 3531.6
  Top w3.94: J3.16@4075.99,3185.83 4075.98,3161.42 4072.05,3157.48 4072.05,1484.48 4067.24,1479.67 4058.07,1479.67 4055.12,1476.72 4055.12,1466.87 4058.07,1463.92 4079.05,1463.92 4086.61,1456.36 4086.61,1439.99 4079.05,1432.43 4058.07,1432.43 4055.12,1429.47 4055.12,1419.63 4058.07,1416.68 4079.05,1416.68 4086.61,1409.11 4086.61,1392.75 4079.05,1385.18 4058.07,1385.18 4055.12,1382.23 4055.12,1372.39 4058.07,1369.43 4079.05,1369.43 4086.61,1361.87 4086.61,1345.5 4079.05,1337.94 4058.07,1337.94 4055.12,1334.98 4055.12,1325.14 4058.07,1322.19 4079.05,1322.19 4086.61,1314.62 4086.61,1298.26 4079.05,1290.69 4058.07,1290.69 4055.12,1287.74 4055.12,1277.9 4058.07,1274.95 4079.05,1274.95 4086.61,1267.38 4086.61,1251.01 4079.05,1243.45 4058.07,1243.45 4055.12,1240.5 4055.12,1230.65 4058.07,1227.7 4079.05,1227.7 4086.61,1220.14 4086.61,1203.77 4079.05,1196.21 4058.07,1196.21 4055.12,1193.25 4055.12,1183.41 4058.07,1180.46 4079.05,1180.46 4086.61,1172.89 4086.61,1156.53 4079.05,1148.96 4058.07,1148.96 4055.12,1146.01 4055.12,1136.17 4058.07,1133.21 4079.05,1133.21 4086.61,1125.65 4086.61,1109.28 4079.05,1101.72 4058.07,1101.72 4055.12,1098.76 4055.12,1088.92 4058.07,1085.97 4079.05,1085.97 4086.61,1078.4 4086.61,1062.04 4079.05,1054.47 4058.07,1054.47 4055.12,1051.52 4055.12,1041.68 4058.07,1038.72 4079.05,1038.72 4086.61,1031.16 4086.61,1014.79 4079.05,1007.23 4058.07,1007.23 4055.12,1004.28 4055.12,994.43 4058.07,991.48 4064.62,991.48 4072.19,983.92 4072.19,856.16 4077.67,850.68 4077.67,839.37 v1(4077.95,839.37) ; C252.1@4153.54,368.11 4159.45,374.02 4159.45,417.32 4055.12,521.65 4055.12,724.41 4124.02,793.31 4151.57,793.31 v1(4157.48,799.21)
  Bottom w3.94: v1(4077.95,839.37) 4072.05,833.46 4072.05,828.74 4079.92,820.87 4106.3,820.87 4133.86,793.31 4151.57,793.31 v1(4157.48,799.21)
SSTX2N_DP_TX_D3N: C253.1 J3.30 | length 3216.2
  Top w3.94: J3.30@3965.75,3185.83 3965.75,3182.5 3965.75,3161.42 3969.69,3157.48 3969.69,702.25 3979.02,692.91 3990.16,692.91 v1(3996.06,687.01) ; v1(4226.38,687.01) 4220.47,692.91 4206.02,692.91 4177.17,664.06 4177.17,552.47 4194.21,535.43 4230.32,535.43 4370.08,395.67 4370.08,374.02 C253.1@4375.98,368.11
  Bottom w3.94: v1(3996.06,687.01) 4001.97,692.91 4220.47,692.91 v1(4226.38,687.01)
SSTX2P_DP_TX_D3P: C254.1 J3.28 | length 3217.3
  Top w3.94: J3.28@3981.5,3185.83 3981.5,3179.9 3981.5,3161.42 3977.56,3157.48 3977.56,705.51 3982.28,700.79 3990.16,700.79 v1(3996.06,706.69) ; v1(4226.38,706.69) 4220.47,700.79 4202.76,700.79 4169.29,667.32 4169.29,549.21 4190.94,527.56 4227.05,527.56 4362.2,392.41 4362.2,374.02 C254.1@4356.3,368.11
  Bottom w3.94: v1(3996.06,706.69) 4000,702.76 4000,700.79 4220.47,700.79 v1(4226.38,706.69)
TP_DET: J3.82 R234.1 | length 2547.7
  Top w3.94: R234.1@1427.17,2714.57 v1(1427.17,2773.62) ; v1(2629.92,2763.78) 2649.61,2783.46 2691.62,2783.46 2906.19,2998.03 3415.35,2998.03 3444.88,2968.5 3535.43,2968.5 3551.18,2984.25 3551.18,3147.69 3556.3,3152.81 3556.3,3181 J3.82@3556.3,3185.83
  Bottom w3.94: v1(1427.17,2773.62) 1513.78,2773.62 1529.53,2789.37 2541.34,2789.37 2551.18,2779.53 2551.18,2753.94 2557.09,2748.03 2614.17,2748.03 v1(2629.92,2763.78)
TP_INT_L: J3.88 R259.1 | length 2296.5
  Top w3.94: v1(1700.79,2998.03) R259.1@1716.54,2998.03 ; v1(2598.43,2763.78) 2627.95,2793.31 2688.36,2793.31 2902.93,3007.87 3421.26,3007.87 3450.79,2978.35 3492.13,2978.35 3509.06,2995.28 3509.06,3184.1 J3.88@3509.06,3185.83
  Bottom w3.94: v1(1700.79,2998.03) 1795.28,2998.03 1811.02,2982.28 1811.02,2872.05 1874.02,2809.06 2553.15,2809.06 v1(2598.43,2763.78)
TP_INT_LCD: D25.1 R259.2 U20.25 | length 423.6
  Top w3.94: v1(1606.3,3285.43) U20.25@1606.3,3331.89 ; v1(1685.04,3098.43) 1694.88,3098.43 D25.1@1722.44,3070.87 1742.13,3051.18 1742.13,3023.62 1742.13,3003.94 R259.2@1736.22,2998.03
  Bottom w3.94: v1(1606.3,3285.43) 1592.52,3271.65 1592.52,3167.32 1661.42,3098.43 v1(1685.04,3098.43)
TP_RST_L: J3.90 R260.1 | length 2215.4
  Top w3.94: v1(1763.78,2982.28) R260.1@1763.78,2998.03 ; v1(2566.93,2763.78) 2606.3,2803.15 2685.04,2803.15 2899.61,3017.72 3427.17,3017.72 3456.69,2988.19 3487.4,2988.19 3493.31,2994.09 3493.31,3181.2 J3.90@3493.31,3185.83
  Bottom w3.94: v1(1763.78,2982.28) 1787.4,2982.28 1801.18,2968.5 1801.18,2866.14 1868.11,2799.21 2545.28,2799.21 2566.93,2777.56 v1(2566.93,2763.78)
TP_RST_LCD: D28.1 R260.2 U20.23 | length 444.7
  Top w3.94: v1(1620.08,3261.81) 1629.92,3271.65 U20.23@1629.92,3331.89 ; v1(1667.32,3118.11) 1714.57,3118.11 D28.1@1761.81,3070.87 1783.46,3049.21 R260.2@1783.46,2998.03
  Bottom w3.94: v1(1620.08,3261.81) 1606.3,3248.03 1606.3,3179.13 v1(1667.32,3118.11)
TP_SCL_LCD: D26.1 R256.2 U20.27 | length 364.8
  Top w3.94: R256.2@1551.18,2998.03 1570.87,3017.72 1570.87,3051.18 D26.1@1551.18,3070.87 v1(1551.18,3092.52) ; v1(1582.68,3285.43) U20.27@1582.68,3331.89
  Bottom w3.94: v1(1551.18,3092.52) 1584.65,3125.98 1584.65,3267.62 1582.68,3269.59 v1(1582.68,3285.43)
TP_SDA_LCD: D27.1 R258.2 U20.26 | length 236.3
  Top w3.94: R258.2@1590.55,2998.03 1607.46,3014.94 1607.46,3053.96 D27.1@1590.55,3070.87 1590.55,3082.68 1594.49,3086.61 U20.26@1594.49,3218.71
TR0: J6.11 J7.2 | length 2297.5
  Top w35.43: v1(1637.8,1190.94) v1(1637.8,1210.63) v1(1653.54,1226.38) 1700.79,1273.62 1897.64,1273.62 2161.42,1537.4 2161.42,1703.54 2194.88,1737.01 J7.2@2234.25,1737.01
  Power w3.94: v1(1637.8,1190.94) 1655.51,1190.94 1655.51,1226.38 v1(1653.54,1226.38)
  Power w35.43: v1(1653.54,1226.38) v1(1637.8,1210.63) v1(1637.8,1190.94) 1637.8,1179.13 2423.23,393.7 2506.69,393.7 J6.11@2551.18,349.21
TR1: J6.12 J7.1 | length 2999.6
  Top w3.94: v1(1580.71,1210.63) v1@1580.71,1212.6
  Top w35.43: v1(1580.71,1190.94) v1(1580.71,1210.63) ; v1@1580.71,1212.6 v1(1580.71,1230.32) 1665.35,1314.96 1874.02,1314.96 2112.2,1553.15 2112.2,1724.41 2179.13,1791.34 2279.92,1791.34 J7.1@2334.25,1737.01
  Power w35.43: v1(1580.71,1230.32) v1(1580.71,1210.63) v1(1580.71,1190.94) 1580.71,1169.29 2379.92,370.08 2379.92,200.79 2480.32,100.39 2615.75,100.39 2651.18,135.83 J6.12@2651.18,299.21
TR2: J6.13 J7.4 | length 2375.8
  Top w3.94: 1724.41,1196.85 v1(1730.32,1190.94)
  Top w35.43: 1724.41,1196.85 1759.84,1232.28 1921.26,1232.28 2177.17,1488.19 2212.6,1488.19 2234.25,1509.84 J7.4@2234.25,1637.01
  Power w3.94: v1(1712.6,1200.79) 1714.81,1203 v1@1730.32,1203 ; 1730.32,1177.17 v1(1730.32,1190.94)
  Power w35.43: 1730.32,1177.17 1730.32,1149.61 2437.01,442.91 2533.46,442.91 2624.02,352.36 2848.03,352.36 J6.13@2901.18,299.21 ; v1(1730.32,1190.94) 1730.32,1203 v1(1730.32,1208.66)
TR3: J6.14 J7.3 | length 2457.6
  Top w35.43: v1(1781.5,1190.94) v1(1820.87,1190.94) 1942.91,1190.94 2191.34,1439.37 2287.4,1439.37 2334.25,1486.22 J7.3@2334.25,1637.01
  Power w3.94: v1@1818.9,1190.94 v1(1820.87,1190.94)
  Power w35.43: v1(1781.5,1190.94) v1(1801.18,1190.94) v1@1818.9,1190.94 ; v1(1820.87,1190.94) 1820.87,1124.02 2450.79,494.09 2826.77,494.09 2852.36,468.5 2852.36,427.17 2930.32,349.21 J6.14@3001.18,349.21
TYPEC0_AUXM: C250.2 D49.2 J15.B8 R339.2 R341.1 | length 761.6
  Top w3.94: C250.2@3980.31,403.54 R339.2@3980.31,377.95 R341.1@3980.31,352.36 3980.32,305.12 D49.2@3960.63,285.43 3938.98,263.78 3938.98,23.62 3980.32,-17.72 4183.07,-17.72 4194.88,-5.91 J15.B8@4194.88,80.71
TYPEC0_AUXP: C249.2 D50.2 J15.A8 R338.2 R340.1 | length 512.5
  Top w3.94: C249.2@4007.87,403.54 R338.2@4007.87,377.95 R340.1@4007.87,352.36 4007.87,305.12 D50.2@4027.56,285.43 v1(4027.56,265.75) ; J15.A8@4263.78,143.7 4263.78,212.6 v1(4283.46,232.28)
  Bottom w3.94: v1(4027.56,265.75) 4250,265.75 v1(4283.46,232.28)
TYPEC0_CC1: C257.1 D47.2 J15.A5 U36.10 U36.11 | length 1006.7
  Top w3.94: v1(3984.25,588.58) 3984.25,498.03 4055.12,427.17 v1(4055.12,238.19) ; v1(4185.04,232.28) 4204.72,212.6 J15.A5@4204.72,143.7 ; U36.10@4251.57,616.14 D47.2@4206.69,616.14 v1(4206.69,588.58) C257.1@4206.69,572.83 4259.84,572.83 4269.69,582.68 U36.11@4269.69,588.19
  Bottom w3.94: v1(3984.25,588.58) v1(4206.69,588.58) ; v1(4055.12,238.19) 4072.83,255.91 4161.42,255.91 v1(4185.04,232.28)
TYPEC0_CC2: C258.1 D48.2 J15.B5 U36.1 U36.14 | length 1055.2
  Top w3.94: J15.B5@4253.94,80.71 4253.94,-5.91 4267.72,-19.68 4425.2,-19.68 4468.5,23.62 4468.5,159.45 4403.54,224.41 4403.54,519.69 D48.2@4374.02,549.21 ; U36.14@4328.74,588.19 4328.74,568.9 4340.55,557.09 C258.1@4340.55,549.21 D48.2@4374.02,549.21 ; U36.1@4346.85,616.14 4364.17,616.14 4374.02,606.3 D48.2@4374.02,549.21
TYPEC0_OTGDM: D46.2 J15.A7 J15.B7 L31.1 R343.2 | length 465.5
  Top w3.94: v1(4214.57,51.18) J15.B7@4214.57,80.71 ; J15.A7@4244.09,143.7 v1(4244.09,171.26) 4238.19,177.17 4238.19,234.25 D46.2@4261.81,257.87 4244.09,257.87 4238.19,263.78 4238.19,326.76 L31.1@4245.08,333.66 4244.09,333.66 R343.2@4244.09,348.43
  Bottom w3.94: v1(4214.57,51.18) 4220.47,45.28 4220.47,36.73 4215.24,31.5 4206.02,31.5 4198.82,38.69 4198.82,57.42 4238.19,96.79 4238.19,165.35 v1(4244.09,171.26)
TYPEC0_OTGDP: D51.2 J15.A6 J15.B6 L31.2 R345.2 | length 490.4
  Top w3.94: J15.A6@4224.41,143.7 v1(4224.41,171.26) 4230.32,177.17 4230.32,234.25 D51.2@4206.69,257.87 4222.44,257.87 4230.32,265.75 4230.32,326.76 L31.2@4223.42,333.66 4224.41,333.66 R345.2@4224.41,348.43 ; v1(4234.25,51.18) J15.B6@4234.25,80.71
  Bottom w3.94: v1(4224.41,171.26) 4230.32,165.35 4230.32,100.06 4190.94,60.69 4190.94,35.43 4202.76,23.62 4218.5,23.62 4228.35,33.46 4228.35,45.28 v1(4234.25,51.18)
TYPEC0RX1N: J15.B10 R346.2 U34.1 U34.10 | length 872.6
  Top w3.94: R346.2@4094.49,348.43 4100.39,342.52 4100.39,316.93 4094.49,311.02 U34.10@4094.49,294.78 U34.1@4094.49,260.34 4094.49,250.99 4100.4,245.08 4100.4,212.26 4081.05,192.91 3975.09,192.91 3964.57,182.4 3964.57,181.44 3964.57,167.32 3970.47,161.42 4016.73,161.42 4019.69,158.46 4019.69,148.62 4016.73,145.67 3972.13,145.67 3964.57,138.1 3964.57,121.74 3972.13,114.17 4010.83,114.17 4013.78,111.22 4013.78,101.38 4010.83,98.43 3972.13,98.43 3964.57,90.86 3964.57,74.49 3972.13,66.93 3989.17,66.93 3992.13,63.98 3992.13,25.93 4004.27,13.78 4125.98,13.78 4149.61,37.4 4149.61,53.15 4155.51,59.06 J15.B10@4155.51,80.71
TYPEC0RX1P: J15.B11 R347.2 U34.2 U34.9 | length 854.3
  Top w3.94: R347.2@4114.17,348.43 4108.27,342.52 4108.27,316.93 4114.18,311.02 U34.9@4114.18,294.78 U34.2@4114.18,260.34 4114.18,250.99 4108.27,245.08 4108.27,209 4084.31,185.04 4061.02,185.04 4051.18,175.2 4043.31,175.2 4033.46,185.04 3978.35,185.04 3972.44,179.13 3972.44,171.26 3974.41,169.29 4019.99,169.29 4027.56,161.73 4027.56,145.36 4019.99,137.8 3975.39,137.8 3972.44,134.84 3972.44,125 3975.39,122.05 4014.09,122.05 4021.65,114.48 4021.65,98.12 4014.09,90.55 3975.39,90.55 3972.44,87.6 3972.44,77.76 3975.39,74.8 3992.43,74.8 4000,67.24 4000,29.19 4007.54,21.65 4122.72,21.65 4141.73,40.66 4141.73,53.15 4135.83,59.06 J15.B11@4135.83,80.71
TYPEC0RX2N: J15.A10 R348.2 U35.1 U35.10 | length 217
  Top w3.94: R348.2@4297.24,348.43 4303.15,342.52 4303.15,316.93 4297.24,311.02 U35.10@4297.24,294.78 U35.1@4297.24,260.34 4297.24,250.99 4303.15,245.08 4303.15,206.69 4309.06,200.79 4309.06,171.26 4303.15,165.35 J15.A10@4303.15,143.7
TYPEC0RX2P: J15.A11 R349.2 U35.2 U35.9 | length 217
  Top w3.94: R349.2@4316.93,348.43 4311.02,342.52 4311.02,316.93 4316.93,311.02 U35.9@4316.93,294.78 U35.2@4316.93,260.34 4316.93,250.99 4311.03,245.08 4311.03,209.95 4316.93,204.05 4316.93,171.26 4322.83,165.35 J15.A11@4322.83,143.7
TYPEC0TX1N: C251.2 J15.A3 U34.5 U34.6 | length 217.8
  Top w3.94: J15.A3@4165.35,143.7 4165.35,165.35 4159.45,171.26 4159.45,183.41 4167.32,191.28 4167.32,245.08 4173.23,250.99 U34.5@4173.23,260.34 U34.6@4173.23,294.78 4173.23,311.02 4167.32,316.93 4167.32,342.52 C251.2@4173.23,348.43
TYPEC0TX1P: C252.2 J15.A2 U34.4 U34.7 | length 217.8
  Top w3.94: J15.A2@4145.67,143.7 4145.67,165.35 4151.57,171.26 4151.57,186.67 4159.45,194.54 4159.45,245.08 4153.54,250.99 U34.4@4153.54,260.34 U34.7@4153.54,294.78 4153.54,311.02 4159.45,316.93 4159.45,342.52 C252.2@4153.54,348.43
TYPEC0TX2N: C253.2 J15.B3 U35.5 U35.6 | length 537
  Top w3.94: J15.B3@4293.31,80.71 4293.31,59.06 4299.21,53.15 4299.21,43.31 4328.74,13.78 4395.67,13.78 4438.98,57.09 4438.98,139.76 4370.08,208.66 4370.08,245.08 4375.98,250.99 U35.5@4375.98,260.34 U35.6@4375.98,294.78 4375.98,311.02 4370.08,316.93 4370.08,342.52 C253.2@4375.98,348.43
